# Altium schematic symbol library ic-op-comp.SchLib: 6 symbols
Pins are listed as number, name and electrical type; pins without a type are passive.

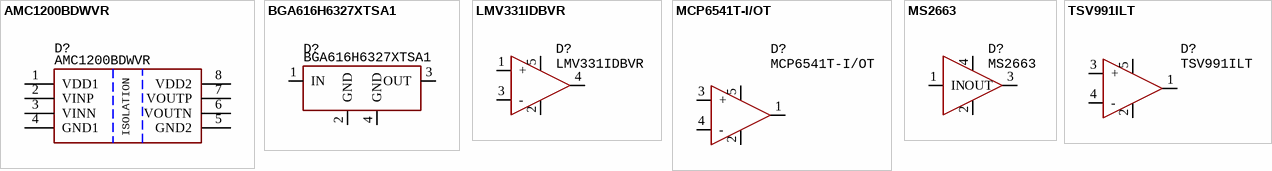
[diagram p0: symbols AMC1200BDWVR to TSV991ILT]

## AMC1200BDWVR
designator D?
IC Amplifier, 4250Vrms, 100 kHz, supply 2.7...5.5V, SOIC-8, -40...+85°C; Manufacture: Texas Instruments
footprint 8-SOIC-W (pitch 1.27 mm, isolator)
pins: 1 VDD1, 2 VINP, 3 VINN, 4 GND1, 5 GND2, 6 VOUTN, 7 VOUTP, 8 VDD2

## BGA616H6327XTSA1
designator D?
IC RF Amplifier, 0...2.7 GHz, 19 dB, supply 6V, SOT-343-4, -40...+85°C; Manufacture: Infineon
footprint SOT343
pins: 1 IN, 2 GND, 3 OUT, 4 GND

## LMV331IDBVR
designator D?
IC Comparator, Push-Pull, 77ns, 1.8...5.5V, SOT-23-5, -40...+85°C; Manufacturer: Tech Public
footprint SOT23-5 (pitch 0.95 mm)
pins: 1 +, 2 GND, 3 -, 4 OUT, 5 VDD

## MCP6541T-I/OT
designator D?
IC Comparator, Push-Pull, 8µs, 1.65...5.5V, SOT-23-5, -40...+85°C; Manufacturer: Microchip
footprint SOT23-5 (pitch 0.95 mm)
pins: 1 OUT, 2 GND, 3 +, 4 -, 5 VDD

## MS2663
designator D?
GNSS LNA, 21 dB, 1550...1615 MHz, 1.2...3.6V, SOT-343, -40...+120°C; Manufacturer: Ruimeng
footprint SOT-343
pins: 1 IN, 2 GND, 3 OUT, 4 VDD

## TSV991ILT
designator D?  PartNumber: TSV991ILT
IC Amplifier, 20 MHz, Rail-to-Rail, supply 2.7...5.5V, SOT23-5, -40...+125°C; Manufacturer: STMicroelectronics; ValueManufacturerPartNumber: IC op amplifier, Rail-to-Rail, 20 MHz, 2.7...5.5V, -40...+125°C, SOT23-5; GainBandwidth: 20 MHz
footprint SOT23-5 (pitch 0.95 mm)
pins: 1 (power), 2 (power), 3 +, 4 -, 5 (power)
